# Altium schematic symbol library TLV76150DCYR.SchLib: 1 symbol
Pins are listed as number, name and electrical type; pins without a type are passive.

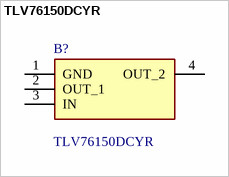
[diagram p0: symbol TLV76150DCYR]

## TLV76150DCYR
designator B?
Linear Voltage Regulators 1-A 16-V high-PSRR linear voltage regulator; Manufacturer_Name: Texas Instruments; Geometry.Height: 1.8mm
footprint SOT230P700X180-4N
pins: 1 GND, 2 OUT_1, 3 IN, 4 OUT_2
